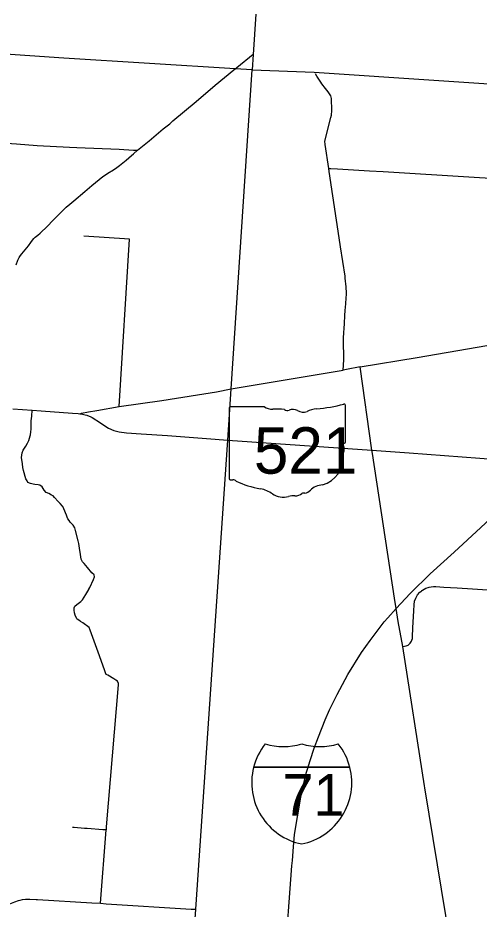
# Model space of a CAD drawing. Extents: x 1729596 to 1925846, y 659247 to 911751.
# Drawn here: x 1841732 to 1855559, y 833985 to 860705 of the extents above; entities that cross this region are included whole.
import ezdxf

# ---------------------------------------------------------------- set-up
doc = ezdxf.new("R2010")
doc.units = 0
for name, color, linetype in [('GM_X_County', 7, 'Continuous'), ('GM_X_County_Road', 7, 'Continuous'), ('GM_X_Interstate_Route', 7, 'Continuous'), ('GM_X_Interstate_Shield', 7, 'Continuous'), ('GM_X_State_Route', 7, 'Continuous'), ('GM_X_State_Shield', 7, 'Continuous'), ('GM_X_Township', 7, 'Continuous'), ('GM_X_Township_Road', 7, 'Continuous')]:
    doc.layers.add(name, color=color, linetype=linetype)

msp = doc.modelspace()

# ---------------------------------------------------------------- linework, layer by layer
at = {"layer": 'GM_X_County'}
msp.add_lwpolyline([(1848864, 860810), (1848787, 859601), (1848752, 859146), (1850615, 859080), (1861827, 858324)], dxfattribs=at)
at = {"layer": 'GM_X_County_Road'}
for points in [[(1848293, 859218), (1848788, 859619)], [(1841678, 853296), (1841734, 853436), (1841775, 853522), (1841811, 853578), (1841852, 853630), (1841955, 853751), (1842050, 853872), (1842120, 853970), (1842174, 854044), (1842213, 854090), (1842257, 854132), (1842328, 854190), (1842398, 854247), (1842454, 854298), (1842569, 854408), (1842835, 854682), (1843009, 854858), (1843082, 854926), (1843184, 855026), (1843290, 855116), (1843408, 855218), (1843743, 855499), (1843955, 855674), (1844282, 855947), (1844355, 856000), (1844431, 856051), (1844597, 856149), (1844696, 856217), (1844777, 856277), (1844977, 856441), (1845142, 856580), (1845198, 856628), (1845320, 856733), (1845665, 857022), (1846093, 857374), (1846284, 857524), (1846382, 857614), (1847073, 858199), (1847645, 858684), (1848208, 859149), (1848243, 859177), (1848285, 859211), (1848293, 859218)], [(1852342, 847746), (1852332, 847819), (1852002, 850172), (1851992, 850242), (1851578, 850159), (1851485, 850140), (1851503, 850457), (1851507, 850519), (1851495, 850994), (1851492, 851085), (1851506, 851296), (1851510, 851368), (1851545, 851947), (1851548, 852007), (1851578, 852429), (1851584, 852517), (1851577, 852569), (1851568, 852637), (1851545, 852900), (1851540, 852956), (1851400, 853843), (1851390, 853908), (1851065, 856102), (1851052, 856192), (1850945, 856903), (1850930, 857004), (1851117, 857720), (1851136, 857792), (1851143, 857929), (1851137, 858286), (1851111, 858362), (1851070, 858431), (1851029, 858488), (1850952, 858587), (1850847, 858724), (1850809, 858773), (1850694, 858953), (1850650, 859027)], [(1851992, 850242), (1853696, 850524), (1855503, 850836), (1856828, 851059), (1859214, 851472), (1860807, 851754), (1861908, 851967)], [(1848128, 849585), (1851485, 850140)], [(1843595, 848838), (1843637, 848852), (1843852, 848894), (1844102, 848937), (1844768, 849049), (1846050, 849232), (1847118, 849400), (1847685, 849497), (1848128, 849585)], [(1846971, 832575), (1846971, 832575), (1847065, 833986), (1848030, 848046), (1848128, 849585)], [(1854821, 832136), (1854806, 832276), (1853927, 837618), (1853916, 837681), (1853270, 841855), (1853135, 842607), (1853071, 843001), (1853019, 843312), (1852359, 847640), (1852342, 847746)]]:
    msp.add_lwpolyline(points, dxfattribs=at)
at = {"layer": 'GM_X_Interstate_Route'}
for points in [[(1853497, 843457), (1854091, 844035), (1854810, 844689), (1856408, 846161), (1857196, 846884), (1857351, 847028)], [(1852825, 842723), (1853071, 843001), (1853486, 843445), (1853497, 843457)], [(1849960, 835440), (1849991, 835852), (1850027, 836225), (1850112, 836751), (1850219, 837345), (1850270, 837606), (1850358, 837993), (1850490, 838443), (1850609, 838810), (1850743, 839153), (1850946, 839662), (1851071, 839958), (1851303, 840416), (1851627, 841020), (1852032, 841680), (1852294, 842043), (1852715, 842598), (1852825, 842723)], [(1849232, 825823), (1849312, 826884), (1849342, 827283), (1849536, 829857), (1849737, 832422), (1849949, 835289), (1849960, 835440)]]:
    msp.add_lwpolyline(points, dxfattribs=at)
at = {"layer": 'GM_X_Interstate_Shield'}
for p, q in [((1848799, 838237), (1851684, 838237)), ((1851684, 838237), (1848799, 838237)), ((1851684, 838237), (1848799, 838237)), ((1848799, 838237), (1851684, 838237)), ((1851684, 838237), (1848799, 838237)), ((1851684, 838237), (1848799, 838237))]:
    msp.add_line(p, q, dxfattribs=at)
for centre, start, end in [((1850616, 837777), 141.669, 165.8066), ((1850616, 837777), 141.669, 165.8066), ((1849693, 840733), 253.0091, 286.9909), ((1849693, 840733), 253.0091, 286.9909), ((1850789, 840733), 253.0091, 286.9909), ((1850789, 840733), 253.0091, 286.9909), ((1849866, 837777), 14.1934, 38.331), ((1849866, 837777), 14.1934, 38.331), ((1850616, 837777), 165.8066, 258.463), ((1850616, 837777), 165.8066, 258.463), ((1849866, 837777), 281.537, 14.1934), ((1849866, 837777), 281.537, 14.1934)]:
    msp.add_arc(centre, 1875, start, end, dxfattribs=at)
at = {"layer": 'GM_X_State_Route'}
for points in [[(1841586, 848982), (1842167, 848948), (1842431, 848928)], [(1842431, 848928), (1843370, 848858), (1843543, 848843)], [(1843543, 848843), (1843595, 848838), (1843668, 848826), (1843754, 848804), (1843796, 848791), (1843824, 848782), (1843899, 848751), (1843959, 848721), (1844210, 848561), (1844336, 848473), (1844448, 848406), (1844608, 848336), (1844771, 848292), (1844988, 848267), (1845431, 848234), (1846221, 848181), (1847382, 848093), (1848030, 848046), (1852342, 847746), (1853462, 847664), (1857695, 847346)]]:
    msp.add_lwpolyline(points, dxfattribs=at)
at = {"layer": 'GM_X_State_Shield'}
for p, q in [((1848068, 849005), (1848068, 846891)), ((1848068, 849005), (1848068, 846891)), ((1849122, 849041), (1848102, 849041)), ((1849122, 849041), (1848102, 849041)), ((1851549, 847988), (1851549, 849093)), ((1851549, 847988), (1851549, 849093)), ((1851548, 847988), (1851549, 847988)), ((1851548, 847988), (1851549, 847988))]:
    msp.add_line(p, q, dxfattribs=at)
for centre, major_axis, start_param, end_param in [((1848108, 849009), (40.3, 0), 1.712693, 3.28349), ((1848108, 849009), (40.3, 0), 1.712693, 3.28349), ((1849364, 849286), (391, 0), 4.042523, 4.731795), ((1849364, 849286), (391, 0), 4.042523, 4.731795), ((1849494, 847855), (1404, 0), 1.404758, 1.657858), ((1849494, 847855), (1404, 0), 1.404758, 1.657858), ((1849813, 849020), (113, 0), 3.836095, 5.185415), ((1849813, 849020), (113, 0), 3.836095, 5.185415), ((1849978, 848776), (235, 0), 0.950623, 2.079405), ((1849978, 848776), (235, 0), 0.950623, 2.079405), ((1850281, 849111), (282, 0), 4.081561, 5.145723), ((1850281, 849111), (282, 0), 4.081561, 5.145723), ((1850780, 848395), (743, 0), 1.699011, 2.107814), ((1850780, 848395), (743, 0), 1.699011, 2.107814), ((1850309, 851922), (3691, 0), 4.814394, 5.042369), ((1850309, 851922), (3691, 0), 4.814394, 5.042369), ((1851510, 849098), (38.7, 0), 6.141152, 7.989035), ((1851510, 849098), (38.7, 0), 6.141152, 7.989035), ((1851540, 847907), (60, 0), 1.883978, 3.671073), ((1851540, 847907), (60, 0), 1.883978, 3.671073), ((1851158, 847767), (360, 0), 5.934695, 6.695948), ((1851158, 847767), (360, 0), 5.934695, 6.695948), ((1851507, 847984), (41.5, 0), 5.05454, 6.418171), ((1851507, 847984), (41.5, 0), 5.05454, 6.418171), ((1851687, 847525), (262, 0), 2.387724, 3.262537), ((1851687, 847525), (262, 0), 2.387724, 3.262537), ((1850515, 847385), (923, 0), 5.101752, 6.440018), ((1850515, 847385), (923, 0), 5.101752, 6.440018), ((1848108, 846887), (40.7, 0), 3.00124, 4.508301), ((1848108, 846887), (40.7, 0), 3.00124, 4.508301), ((1848115, 847103), (310, 0), 4.665946, 4.897461), ((1848115, 847103), (310, 0), 4.665946, 4.897461), ((1848178, 846769), (112, 0), 0.519207, 1.627899), ((1848178, 846769), (112, 0), 0.519207, 1.627899), ((1849591, 848668), (2665, 0), 4.195997, 4.488961), ((1849591, 848668), (2665, 0), 4.195997, 4.488961), ((1848797, 845942), (834, 0), 0.823519, 1.323587), ((1848797, 845942), (834, 0), 0.823519, 1.323587), ((1850264, 846686), (298, 0), 4.937069, 5.64225), ((1850264, 846686), (298, 0), 4.937069, 5.64225), ((1850905, 846298), (506, 0), 1.647645, 2.488434), ((1850905, 846298), (506, 0), 1.647645, 2.488434), ((1849699, 846759), (529, 0), 4.026481, 4.996735), ((1849699, 846759), (529, 0), 4.026481, 4.996735), ((1850004, 846028), (435, 0), 1.495662, 1.94098), ((1850004, 846028), (435, 0), 1.495662, 1.94098), ((1850043, 846601), (282, 0), 4.691044, 5.507374), ((1850043, 846601), (282, 0), 4.691044, 5.507374), ((1850298, 846396), (79.4, 0), 1.147584, 2.315152), ((1850298, 846396), (79.4, 0), 1.147584, 2.315152)]:
    msp.add_ellipse(centre, major_axis=major_axis, ratio=0.8, start_param=start_param, end_param=end_param, dxfattribs=at)
at = {"layer": 'GM_X_Township'}
for points in [[(1848864, 860810), (1848787, 859601), (1848752, 859146), (1848243, 859177), (1843111, 859493), (1837275, 859897), (1836785, 859928), (1833125, 860220), (1832799, 860239), (1832694, 860243), (1830166, 860402), (1830089, 860410), (1830057, 860416), (1824857, 860710)], [(1858606, 831851), (1854821, 832136), (1851310, 832334), (1849737, 832422), (1846971, 832575), (1847065, 833986), (1848030, 848046), (1848128, 849585), (1848752, 859146), (1850615, 859080), (1861827, 858324)]]:
    msp.add_lwpolyline(points, dxfattribs=at)
at = {"layer": 'GM_X_Township_Road'}
for points in [[(1840298, 857042), (1840462, 857025), (1841078, 856968), (1841688, 856928), (1842311, 856878), (1843277, 856832), (1843501, 856817), (1844772, 856764), (1845200, 856735), (1845320, 856733)], [(1851052, 856192), (1851109, 856192), (1851317, 856179), (1852272, 856121), (1852677, 856096), (1855405, 855928), (1855903, 855897), (1856892, 855832)], [(1844768, 849049), (1845076, 854067), (1843711, 854157), (1843711, 854157)], [(1843111, 845983), (1843107, 845993), (1843076, 846068), (1843002, 846144), (1842938, 846209), (1842834, 846328), (1842792, 846377), (1842745, 846400), (1842658, 846443), (1842580, 846479), (1842518, 846549), (1842493, 846596), (1842466, 846646), (1842396, 846696), (1842344, 846704), (1842246, 846720), (1842194, 846729), (1842110, 846744), (1842034, 846776), (1842009, 846822), (1841976, 846884), (1841907, 847139), (1841882, 847229), (1841869, 847334), (1841860, 847401), (1841852, 847454), (1841840, 847528), (1841863, 847661), (1841896, 847749), (1841968, 847865), (1842022, 847959), (1842058, 848032), (1842084, 848101), (1842105, 848172), (1842112, 848208), (1842126, 848296), (1842134, 848374), (1842137, 848623), (1842150, 848766), (1842167, 848948)], [(1843823, 844224), (1843717, 844351), (1843674, 844402), (1843630, 844475), (1843602, 844684), (1843594, 844739), (1843558, 844947), (1843544, 845028), (1843460, 845334), (1843438, 845415), (1843386, 845501), (1843361, 845526), (1843349, 845538), (1843298, 845589), (1843268, 845633), (1843228, 845691), (1843209, 845741), (1843188, 845798), (1843111, 845983)], [(1843771, 843420), (1843860, 843570), (1843863, 843575), (1843892, 843625), (1843997, 843867), (1844030, 843945), (1844022, 844005), (1843954, 844068), (1843823, 844224)], [(1853844, 843535), (1853861, 843548), (1853911, 843579), (1853965, 843605), (1854028, 843627), (1854060, 843636), (1854125, 843648), (1854191, 843655), (1854258, 843655), (1854503, 843639), (1854896, 843613), (1855969, 843548)], [(1843677, 842566), (1843609, 842613), (1843559, 842648), (1843513, 842674), (1843503, 842690), (1843491, 842712), (1843453, 842794), (1843429, 842865), (1843423, 842949), (1843423, 843023), (1843441, 843067), (1843499, 843117), (1843540, 843150), (1843617, 843209), (1843675, 843258), (1843771, 843420)], [(1853270, 841855), (1853375, 841876), (1853430, 841904), (1853489, 841960), (1853510, 841987), (1853529, 842020), (1853540, 842047), (1853556, 842102), (1853564, 842152), (1853571, 842416), (1853597, 842931), (1853607, 843104), (1853625, 843215), (1853660, 843313), (1853709, 843404), (1853779, 843484), (1853838, 843531), (1853844, 843535)], [(1844215, 834160), (1844384, 836360), (1844385, 836371), (1844391, 836449), (1844748, 840708), (1844751, 840754), (1844719, 840820), (1844674, 840847), (1844607, 840886), (1844427, 840996), (1844381, 841024), (1844362, 841073), (1844329, 841160), (1844136, 841693), (1843898, 842352), (1843869, 842432), (1843677, 842566)], [(1843367, 836442), (1843417, 836439), (1843733, 836416), (1843809, 836411), (1844283, 836378), (1844385, 836371)], [(1839872, 834185), (1840004, 834176), (1840213, 834155), (1840314, 834142), (1840419, 834128), (1840709, 834086), (1840854, 834066), (1840955, 834057), (1841058, 834052), (1841152, 834058), (1841236, 834072), (1841340, 834101), (1841488, 834149), (1841639, 834205), (1841751, 834242), (1841801, 834256), (1841870, 834271), (1841962, 834284), (1842018, 834287), (1842093, 834287), (1842280, 834278)], [(1842280, 834278), (1842320, 834277), (1843950, 834176), (1844215, 834160), (1844383, 834149), (1846926, 833987), (1847065, 833986)]]:
    msp.add_lwpolyline(points, dxfattribs=at)

# ---------------------------------------------------------------- texts
at = {"layer": 'GM_X_Interstate_Shield'}
msp.add_text('71', height=1250, dxfattribs=at).set_placement((1849664, 836784))
msp.add_text('71', height=1250, dxfattribs=at).set_placement((1849664, 836784))
at = {"layer": 'GM_X_State_Shield'}
msp.add_text('521', height=1392.2, dxfattribs=at).set_placement((1848805, 847040))
msp.add_text('521', height=1392.2, dxfattribs=at).set_placement((1848805, 847040))

doc.saveas('drawing.dxf')
